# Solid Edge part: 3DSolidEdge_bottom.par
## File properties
Author: Administrator
Last saved by: Administrator
Revision: 49
Accuracy: 0.990
Agile_Description: Bottom Part
Modeled_By: L. Conard
Part_Number: ITEM-SE-00004
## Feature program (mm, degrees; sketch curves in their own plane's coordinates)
body "unnamed Body 1"
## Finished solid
Body 1: solid body, 58 faces, 138 edges, 84 vertices.
  Faces by surface: plane 30, cylinder 24, sphere 4
  Edges by curve: line 90, circle 48
Bounding box of the edges (mm; curved faces can reach further): 64.000 x 105.000 x 8.000, from (0, 0, -8) to (64, 105, 0).
Cylindrical faces by radius (mm): R0.75 x3, R1 x2, R1.9 x3, R2.54 x4, R2.75 x4, R4 x8
Spherical faces by radius (mm): R4 x4
Planar faces by outward normal: +x 6, +y 5, +z 7, -x 6, -y 5, -z 1
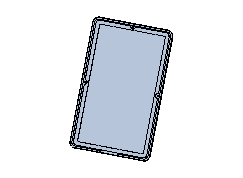
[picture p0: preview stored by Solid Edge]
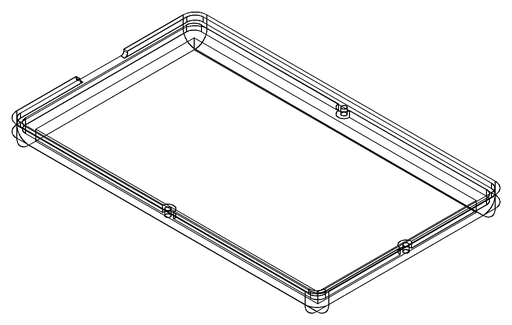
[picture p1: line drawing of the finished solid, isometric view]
